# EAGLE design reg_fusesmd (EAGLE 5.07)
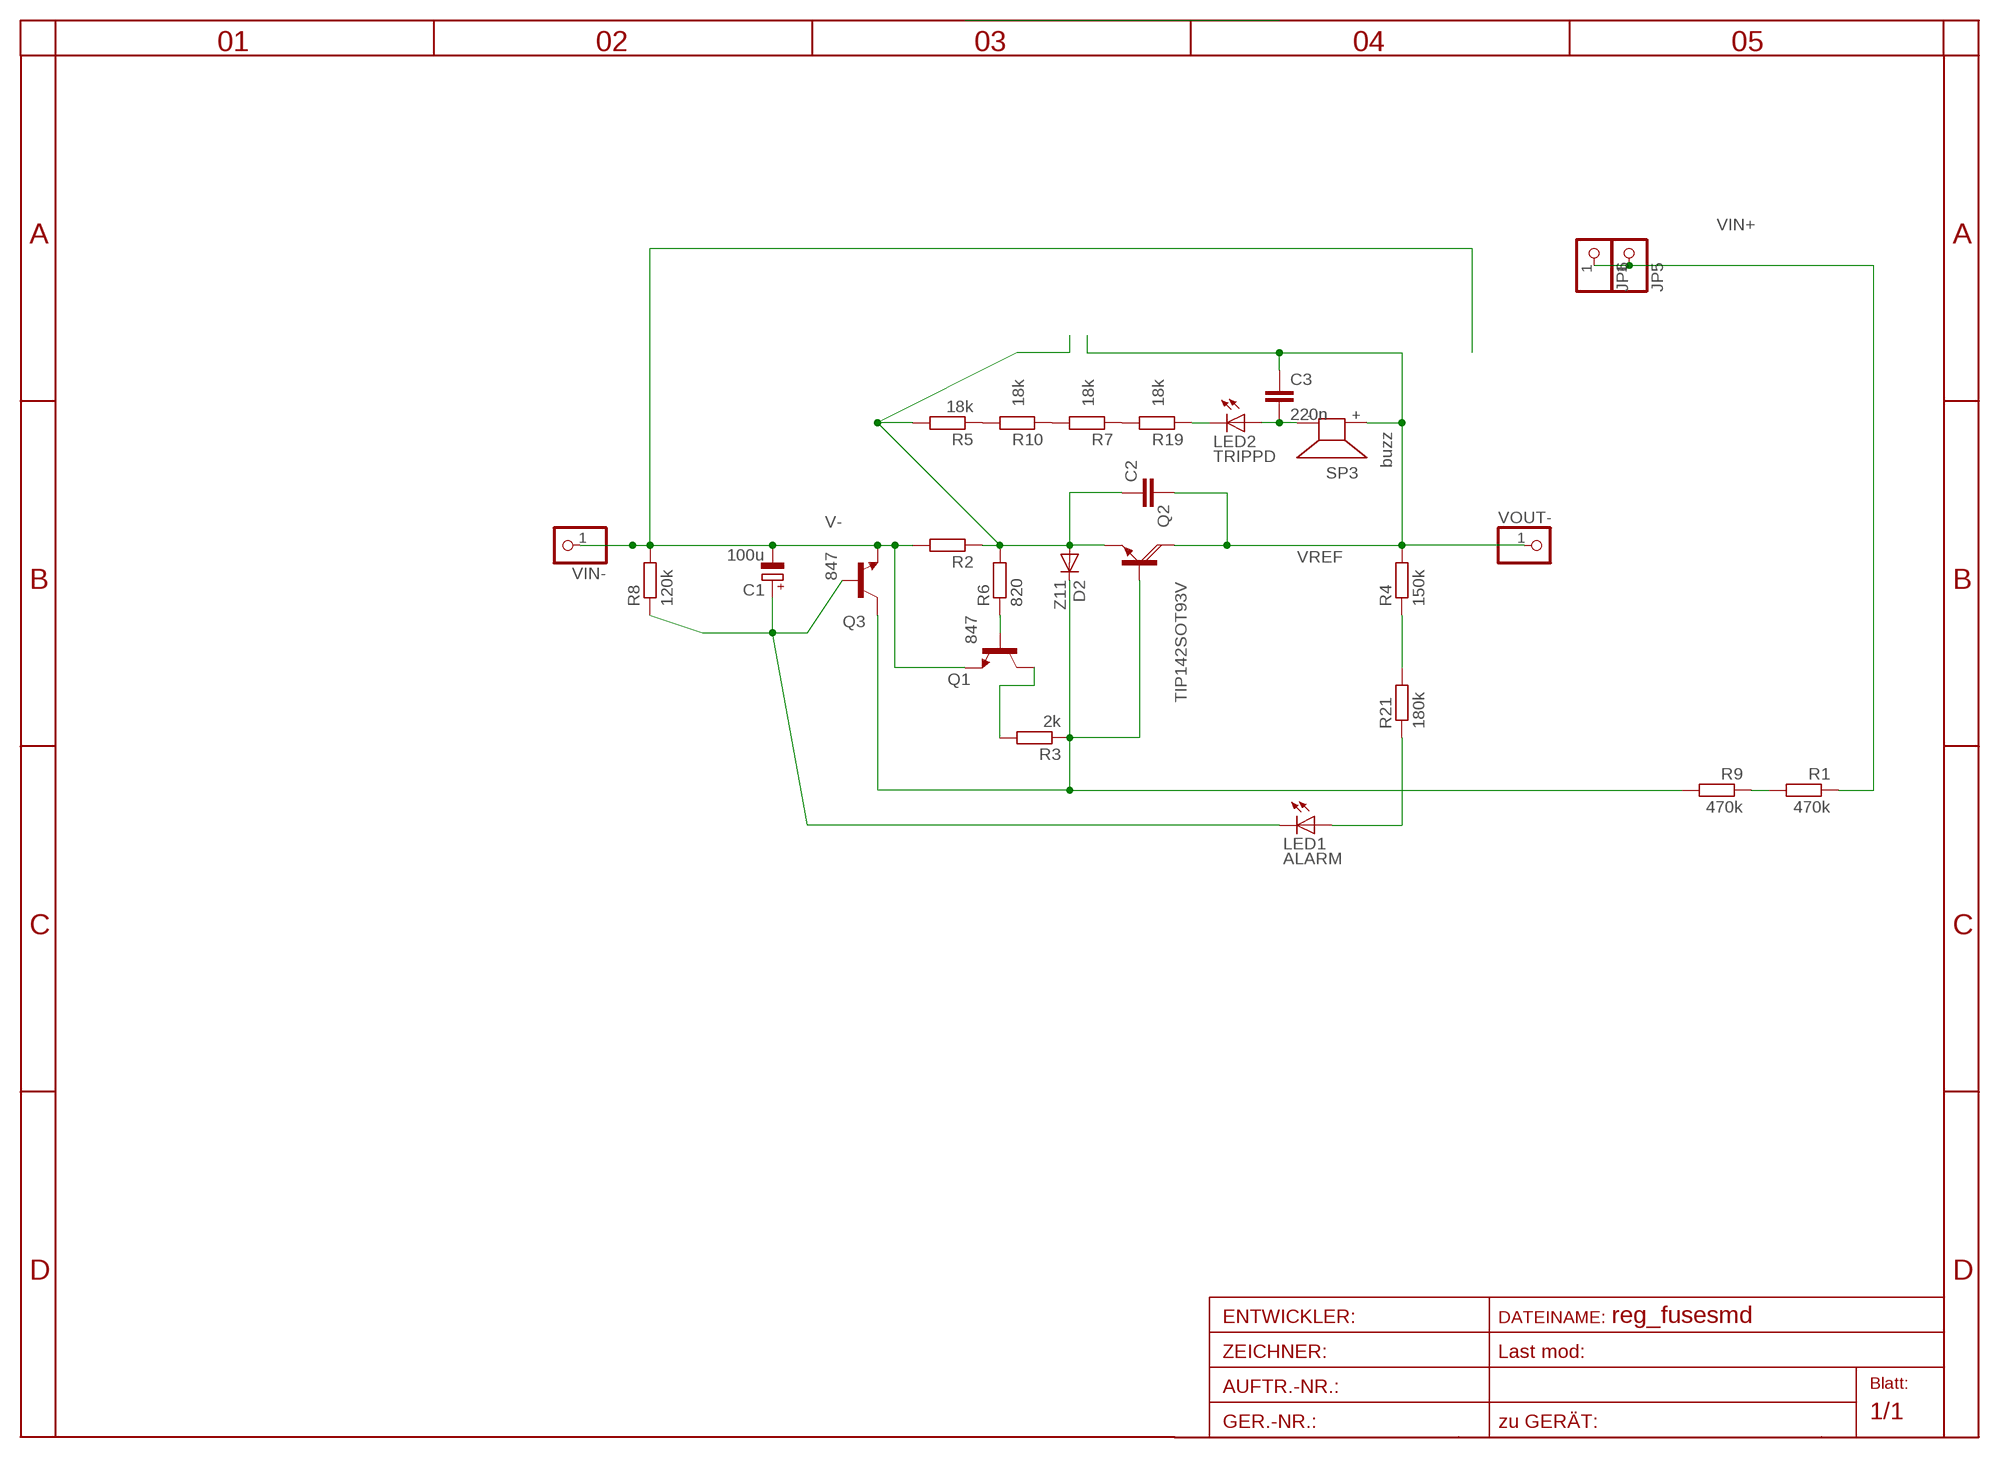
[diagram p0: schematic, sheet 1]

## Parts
C1  100u  CPOL-EUE2.5-5  [E2,5-5]
C2  C-EU225-062X268  [C225-062X268]
C3  220n  C-EUC1206  [C1206]
D2  Z11  DIODE-MINIMELF  [MINIMELF]
JP5  PINHD-1X12MM3  [1X2MM3]
JP6  PINHD-1X12MM3  [1X2MM3]
LED1  ALARM  LED5MM  [LED5MM]
LED2  TRIPPD  LED5MM  [LED5MM]
Q1  847  BC847ALT1SMD  [SOT23]
Q2  TIP142SOT93V  [SOT93V]
Q3  847  BC847ALT1SMD  [SOT23]
R1  470k  R-EU_R1206  [R1206]
R2  R-EU_0411/12  [0411/12]
R3  2k  R-EU_R0805  [R0805]
R4  150k  R-EU_R1206  [R1206]
R5  18k  R-EU_R1206  [R1206]
R6  820  R-EU_R1206  [R1206]
R7  18k  R-EU_R1206  [R1206]
R8  120k  R-EU_R0805  [R0805]
R9  470k  R-EU_R1206  [R1206]
R10  18k  R-EU_R1206  [R1206]
R19  18k  R-EU_R1206  [R1206]
R21  180k  R-EU_R1206  [R1206]
SP3  buzz  KSS12017MM  [KSS1202]
VIN-  PINHD-1X12MM3  [1X2MM3]
VOUT-  PINHD-1X12MM3  [1X2MM3]

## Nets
A1: C3.2 LED2.A SP3.-
E1: C2.1 D2.A Q2.E R2.1 R5.2 R6.2
GATE: D2.C Q2.B Q3.3(C) R3.1 R9.2
N$1: R7.2 R10.1
N$2: R5.1 R10.2
N$6: Q1.1(B) R6.1
N$7: Q1.3(C) R3.2
N$9: LED2.K(C) R19.1
N$11: LED1.A R21.1
N$20: R1.2 R9.1
N$21: R7.1 R19.2
N$22: R4.1 R21.2
SIGN: C1.+ LED1.K(C) Q3.1(B) R8.1
V-: C1.- Q1.2(E) Q3.2(E) R2.2 R8.2 VIN-.1
VIN+: JP5.1 JP6.1 R1.1
VREF: C2.2 C3.1 Q2.C R4.2 SP3.+ VOUT-.1

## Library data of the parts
C1 = rcl:CPOL-EU: POLARIZED CAPACITOR, European symbol
C2 C3 = rcl:C-EU: CAPACITOR, European symbol
D2 = diode:DIODE-: DIODE
JP5 JP6 VIN- VOUT- = pinhead:PINHD-1X1: PIN HEADER
LED1 LED2 = led:LED: LED
Q1 Q3 = transistor-npn:BC847*: NPN Transistor
Q2 = transistor-power:TIP142: NPN DARLINGTON TRANSISTOR
R1 R3-R10 R19 R21 = rcl:R-EU_: RESISTOR, European symbol
R2 = rcl-2:R-EU_: RESISTOR, European symbol
SP3 = buzzer:KSS1201: SPEAKER

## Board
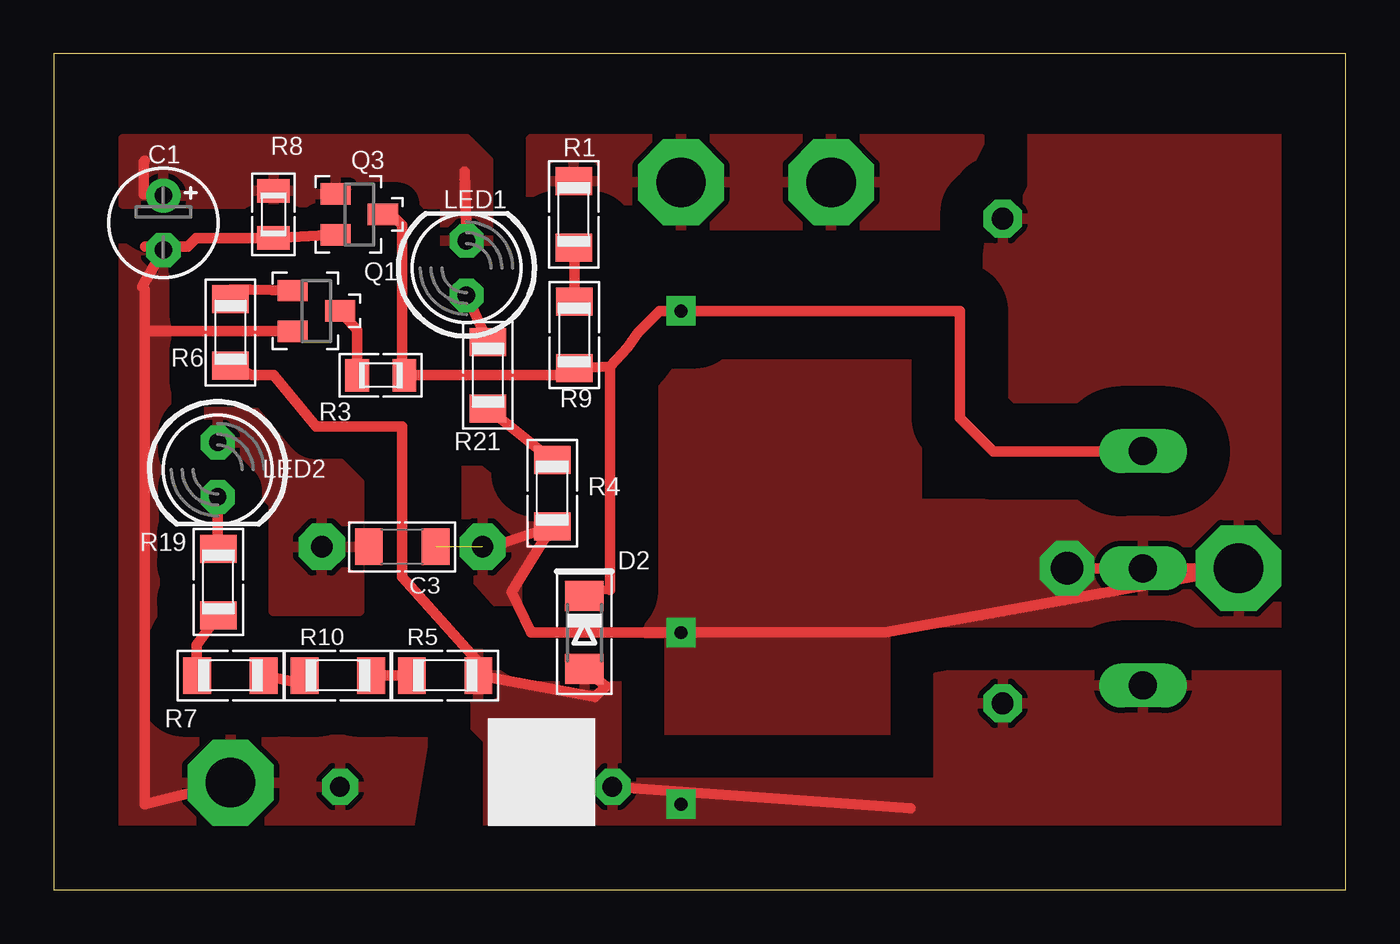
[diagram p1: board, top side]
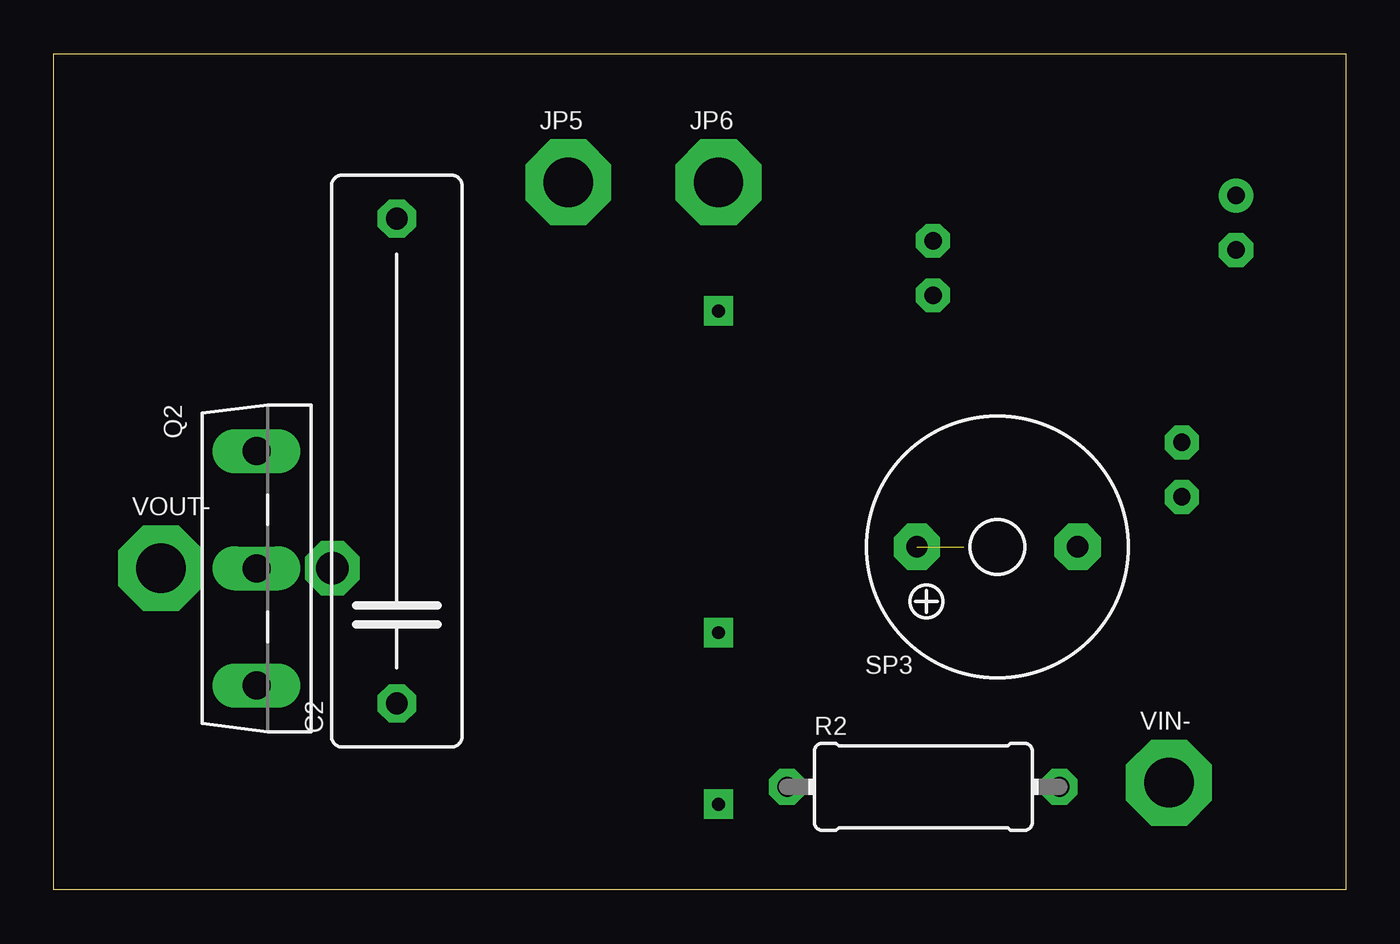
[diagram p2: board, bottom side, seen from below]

Size 60.25 x 39 mm. Coordinates in mm from the lower left corner, seen from the top.
Outline: 60.25,0 60.25,39 0,39 0,0 60.25,0
Copper layers (1*16): Top 0.035mm / dielectric 1.5mm / Bottom 0.035mm
Design rules "default *": minimum track width 10mil, minimum drill 2mil, track to track 8mil, track to pad 8mil, pad to pad 8mil, via to via 8mil, smd to smd 8mil, copper to edge 3mm, drill to drill 8mil, minimum pad ring 15mil, minimum via ring 15mil, stop-mask expansion 4mil, vias tented up to drill 0mil, thermal gap 10mil

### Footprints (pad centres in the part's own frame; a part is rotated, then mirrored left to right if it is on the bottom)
E2,5-5 = drill 0.813 pad 1.6 round: + -1.27,0 | drill 0.813 pad 1.6 octagon: - 1.27,0
C225-062X268 = drill 1.016 octagon: 1 -11.303,0; 2 11.303,0
C1206 = smd 1.3 x 1.7: 1 -1.55,0; 2 1.55,0
MINIMELF = smd 1.4 x 1.8: A 1.7,0; C -1.7,0
1X2MM3 = drill 2.3 pad 4 octagon: 1 0,0
LED5MM = drill 0.813 octagon: A -1.27,0; K 1.27,0
SOT23 = smd 1 x 1.4: 1 -0.95,-1.1; 2 0.95,-1.1; 3 0,1.1
SOT93V = drill 1.3 pad 1.676 long: B -5.461,-2.54; C 0,-2.54; E 5.461,-2.54
R1206 = smd 1.3 x 1.7: 1 -1.55,0; 2 1.55,0
0411/12 = drill 0.914 octagon: 1 -6.35,0; 2 6.35,0
R0805 = smd 1.1 x 1.5: 1 -1.1,0; 2 1.1,0
KSS1202 = drill 1 pad 2.159 octagon: + 3.75,0; - -3.75,0

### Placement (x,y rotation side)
C1  5.12,31.11 270 top
C2  44.25,20 90 bottom
C3  16.25,16 180 top
D2  24.75,12 270 top
JP5  36.25,33 0 bottom
JP6  29.25,33 0 bottom
LED1  19.25,29 90 top
LED2  7.65,19.6 270 top
Q1  12.25,27 270 top
Q2  48.25,15 270 bottom
Q3  14.25,31.5 270 top
R1  24.25,31.5 270 top
R2  19.7,4.81 0 bottom
R3  15.25,24 180 top
R4  23.25,18.5 270 top
R5  18.25,10 0 top
R6  8.25,26 270 top
R7  8.25,10 0 top
R8  10.25,31.5 270 top
R9  24.28,25.88 270 top
R10  13.25,10 0 top
R19  7.68,14.36 270 top
R21  20.25,24 270 top
SP3  16.25,16 180 bottom
VIN-  8.25,5 0 bottom
VOUT-  55.25,15 0 bottom

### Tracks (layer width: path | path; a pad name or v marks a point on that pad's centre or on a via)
A1
  pour Top (isolate 1.27, rank 3): 7.25,23 10.25,23 14.25,19 14.25,13 10.25,13 10.25,18 9.25,19 7.25,19
E1  (via drill 0.6)
  Top 0.5: R2.1 39.95,3.81 | R6.2 9.25,24 10.25,24 12.25,21.6 16.25,21.6 16.25,14.6 19.67,10.78 R5.2 25.25,9 25.75,9.5 D2.A
  other vias: 29.25,4
  pour Top (isolate 2, rank 2): 18.25,11 18.25,8 19.25,8 20.25,7 20.25,2 57.25,2 57.25,10 41.25,10 41.25,5 26.25,5 26.25,11
GATE  (via drill 0.6)
  Top 0.406: 25.95,14 24.75,14 D2.C
  Top 0.5: Q2.B 50.3,20.45 43.81,20.45 42.25,22 42.25,27 v29.25,27 28.25,27 27.25,26 26.75,25.3 25.95,24.4 | 25.95,14 25.95,24.4 | Q3.3 15.75,31.5 16.25,31 16.25,24.05 R3.1 23.95,24 R9.2 24.32,24.33 25.95,24.4
N$1
  Top 0.5: R7.2 11.22,9.71 R10.1
N$2
  Top 0.5: R10.2 R5.1
N$6
  Top 0.5: Q1.1 9.15,28 8.25,28 R6.1
N$7
  Top 0.5: R3.2 14.15,26.1 Q1.3
N$9
  Top 0.5: LED2.K 7.65,16.01 R19.1
N$11
  Top 0.5: LED1.A R21.1
N$20
  Top 0.5: R9.1 24.28,29.97 R1.2
N$21
  Top 0.5: R19.2 6.68,11.44 R7.1
N$22
  Top 0.5: R21.2 R4.1
SIGN
  Top 0.5: LED1.K 19.15,33.5 | C1.+ 4.19,32.45 4.19,33.94 4.25,34
  pour Top (isolate 1, rank 2): 3.25,32 3.25,35 19.25,35 20.25,34 20.25,30 18.25,30 18.25,32
V-
  Top 0.5: VIN-.1 4.25,4 4.25,26 | Q3.2 R8.2 6.65,30.4 6.25,30 4.28,30 C1.- 4.12,28.13 4.25,28 4.25,26.05 | 4.3,26.05 Q1.2 | 4.25,26 4.3,26.05 | 4.3,26.05 4.25,26.05 | 4.25,26 4.25,26.05
  pour Top (isolate 2): 2.25,31 5.25,31 5.25,7 17.25,7 16.25,1 1.25,1
VIN+
  pour Top (isolate 2): 22.25,35 43.25,35 41.25,31 22.25,31
VREF  (via drill 0.6, 1.5 pad 2.54)  (1 unrouted)
  Top 0.5: SP3.+ 20.35,15.98 R4.2 21.35,13.9 22.25,12 v29.25,12 38.75,12 VOUT-.1 | VOUT-.1 v47.25,15 Q2.C VOUT-.1
  pour Top (isolate 2, rank 4): 43.25,35 58.25,35 57.25,12 41.25,12 41.25,7 19.25,7 19.25,25 40.25,25 40.25,18 53.25,18 53.25,22 41.25,22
